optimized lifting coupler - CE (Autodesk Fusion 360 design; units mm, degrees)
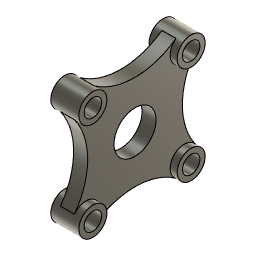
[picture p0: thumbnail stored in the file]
sketch "Sketch1" plane through (0, 0, 0) normal (1, 0, 0) x axis (0, 1, 0)
  circle C1 centre (0, 0) radius 19.05
  circle C2 centre (-44.45, 44.45) radius 7.9375
  circle C3 centre (-44.45, 44.45) radius 12.7
  circle C4 centre (-44.45, -44.45) radius 12.7
  circle C5 centre (-44.45, -44.45) radius 7.9375
  circle C6 centre (44.45, -44.45) radius 12.7
  circle C7 centre (44.45, -44.45) radius 7.9375
  circle C8 centre (44.45, 44.45) radius 12.7
  circle C9 centre (44.45, 44.45) radius 7.9375
  arc A1 centre (-106.3421, 0) radius 63.5 clockwise from (-54.7654, 37.0417) to (-54.7654, -37.0417)
  arc A2 centre (0, -106.3421) radius 63.5 clockwise from (-37.0417, -54.7654) to (37.0417, -54.7654)
  arc A3 centre (106.3421, 0) radius 63.5 clockwise from (54.7654, -37.0417) to (54.7654, 37.0417)
  arc A4 centre (0, 106.3421) radius 63.5 clockwise from (37.0417, 54.7654) to (-37.0417, 54.7654)
  point P1 (0, 0)
  point P2 (0, 0)
  point P12 (-54.7654, -37.0417)
  point P11 (-54.7654, 37.0417)
  point P4 (-44.45, 44.45)
  point P3 (-44.45, 44.45)
  coincident P1 P2
  concentric C2 C3
  coincident C4 P12
  coincident C3 P11
  vertical P11 P12
  tangent C3 A1
  dimension "d1" diameter C1 = 38.1
  dimension "d2" diameter C3 = 25.4
  dimension "d3" diameter C2 = 15.875
  dimension "d4" distance P2 P4 = 44.45
  dimension "d5" distance P1 P3 = 44.45 (= "d4")
  dimension "d10" radius A1 = 63.5
  dimension "d7" C-Pattern1-Angle = 360
  dimension "d9" C-Pattern2-Angle = 360
extrude "Extrude1" new body sketch "Sketch1" distance 6.35
extrude "Extrude2" add sketch "Sketch1" profile of C2 C3 C4 C5 C6 C7 C8 C9 distance 12.7
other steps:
step "Ё"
